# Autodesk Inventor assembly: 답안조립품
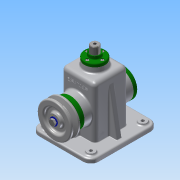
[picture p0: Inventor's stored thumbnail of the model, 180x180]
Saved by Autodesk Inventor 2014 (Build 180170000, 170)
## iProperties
Created: 2016-06
Part Number: 답안조립품
Document SubType Name: Assembly
Designer: Administrator
Author: Administrator
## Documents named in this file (19)
- C:\Users\Administrator\Desktop\Manufacturing2급-김흥기\답안조립품.iam
- C:\Users\Administrator\Desktop\Manufacturing2급-김흥기\1-본체.ipt
- C:\Users\Administrator\Desktop\Manufacturing2급-김흥기\V-벨트풀리.ipt
- C:\Users\Administrator\Desktop\Manufacturing2급-김흥기\고정핀.ipt
- C:\Users\Administrator\Desktop\Manufacturing2급-김흥기\뒤커버.ipt
- C:\Users\Administrator\Desktop\Manufacturing2급-김흥기\링크.ipt
- C:\Users\Administrator\Desktop\Manufacturing2급-김흥기\멈춤링 6 x 5.ipt
- C:\Users\Administrator\Desktop\Manufacturing2급-김흥기\멈춤링 15 x 1.ipt
- C:\Users\Administrator\Desktop\Manufacturing2급-김흥기\베어링 15 x 35 x 11.ipt
- C:\Users\Administrator\Desktop\Manufacturing2급-김흥기\볼트 M3 x 8.ipt
- C:\Users\Administrator\Desktop\Manufacturing2급-김흥기\볼트 M4 x 10.ipt
- C:\Users\Administrator\Desktop\Manufacturing2급-김흥기\볼트 M6 x 12.ipt
- C:\Users\Administrator\Desktop\Manufacturing2급-김흥기\상부부시.ipt
- C:\Users\Administrator\Desktop\Manufacturing2급-김흥기\슬라이드바.ipt
- C:\Users\Administrator\Desktop\Manufacturing2급-김흥기\앞커버.ipt
- C:\Users\Administrator\Desktop\Manufacturing2급-김흥기\오일실 15 25 7.ipt
- C:\Users\Administrator\Desktop\Manufacturing2급-김흥기\와셔.ipt
- C:\Users\Administrator\Desktop\Manufacturing2급-김흥기\키 5 x 5 x 14.ipt
- C:\Users\Administrator\Desktop\Manufacturing2급-김흥기\편심축.ipt
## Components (16 placed, 6 different names)
1. 1-본체:1
2. V-벨트풀리:1
3. 고정핀:1
4. ISO 4018 M6 x 12:1
5. ISO 4762 M4 x 10:2
6. ISO 4762 M4 x 10:3
7. ISO 4762 M4 x 10:4
8. ISO 4762 M4 x 10:5
9. ISO 4762 M4 x 10:1
10. ISO 4762 M4 x 10:6
11. ISO 4762 M4 x 10:7
12. ISO 4762 M4 x 10:8
13. ISO 4762 M3 x 8:1
14. ISO 4762 M3 x 8:2
15. ISO 4762 M3 x 8:3
16. ISO 4762 M3 x 8:4
